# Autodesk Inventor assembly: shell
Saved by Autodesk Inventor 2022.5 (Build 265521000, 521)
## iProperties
Created: 2024-12
Part Number: shell
Document SubType Name: Assembly
Designer: AdminForWorker
Title: shell
Author: AdminForWorker
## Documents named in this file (4)
- c:\worker\convert-fusion-r05-cosv3\tmp\job-1\35\temp\files\545dca92-a972-481a-9197-dd1a1176500e\shell_1.iam
- c:\worker\convert-fusion-r05-cosv3\tmp\job-1\35\temp\files\545dca92-a972-481a-9197-dd1a1176500e\outer.ipt
- c:\worker\convert-fusion-r05-cosv3\tmp\job-1\35\temp\files\545dca92-a972-481a-9197-dd1a1176500e\back_shell.ipt
- c:\worker\convert-fusion-r05-cosv3\tmp\job-1\35\temp\files\545dca92-a972-481a-9197-dd1a1176500e\mid_cover.ipt
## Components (3 placed, 3 different names)
1. outer:1
2. back_shell:1
3. mid_cover:1
